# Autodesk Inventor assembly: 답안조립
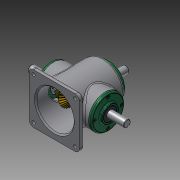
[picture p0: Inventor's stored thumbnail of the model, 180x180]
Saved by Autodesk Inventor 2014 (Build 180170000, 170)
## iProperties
Created: 2015-10
Part Number: 답안조립
Document SubType Name: Assembly
Designer: Administrator
Author: Administrator
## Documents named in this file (14)
- C:\Users\Administrator\Desktop\451007V1021\답안조립.iam
- C:\Users\Administrator\Desktop\451007V1021\1-본체.ipt
- C:\Users\Administrator\Desktop\451007V1021\메인 베벨기어.ipt
- C:\Users\Administrator\Desktop\451007V1021\메인 축.ipt
- 메인 축.ipt
- C:\Users\Administrator\Desktop\451007V1021\베어링 6203.ipt
- C:\Users\Administrator\Desktop\451007V1021\서브 베벨기어.ipt
- C:\Users\Administrator\Desktop\451007V1021\서브 축.ipt
- 서브 축.ipt
- C:\Users\Administrator\Desktop\451007V1021\오일실.ipt
- C:\Users\Administrator\Desktop\451007V1021\커버.ipt
- C:\Users\Administrator\Desktop\451007V1021\키 4x4.ipt
- C:\Users\Administrator\Desktop\451007V1021\키 5x5.ipt
- C:\Users\Administrator\Desktop\451007V1021\M4.ipt
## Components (13 placed, 2 different names)
1. 1-본체:1
2. M4:2
3. M4:3
4. M4:4
5. M4:5
6. M4:1
7. M4:6
8. M4:7
9. M4:8
10. M4:9
11. M4:10
12. M4:11
13. M4:12
## Named parameters: d15_d5 = 0, d16_d9 = 0
